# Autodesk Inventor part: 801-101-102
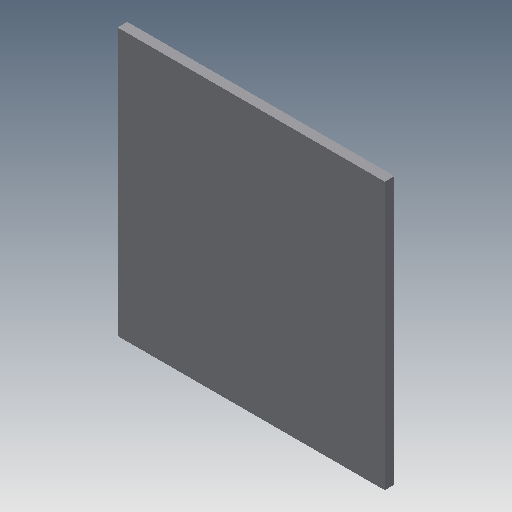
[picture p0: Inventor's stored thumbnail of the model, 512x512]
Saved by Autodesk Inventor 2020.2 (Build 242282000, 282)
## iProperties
Created: 2011-01
Part Number: 801-101-102
Document SubType Name: Modeling
Designer: F.Stasiak
Density: 1 g/cm^3
Material: Ogólny
Appearance: Domyślna
Catalog Web Link: www.expertbooks.pl
Company: Fabian Stasiak CAD Consulting
Manager: www.cadconsulting.pl
Author: F.Stasiak
Subject: Zbiór ćwiczeń. Autodesk Inventor 2020. Kurs Professional
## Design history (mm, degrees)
sketch "Szkic1"
  geometry: L1 (-110, -110)-(110, -110); L2 (110, -110)-(110, 110); L3 (110, 110)-(-110, 110); L4 (-110, 110)-(-110, -110); 3 further points
  constraints: 8 end point, 2 midpoint, 2 parallel, 1 horizontal, 1 horizontal alignment, 1 perpendicular, 1 vertical alignment
  dimensions: "d0" = 220 distance of L1.start L1.end; "d1" = 220 distance of L1.end L2.end (= d0)
extrude "Wyciągnięcie proste1" new body sketch "Szkic1" distance "d2" = 8; taper "d3" = 0 deg
node "Bryła1"
